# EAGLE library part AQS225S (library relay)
PhotoMOS Relay NAiS Source: http://www.mew-europe.com/.. pti_en.pdf
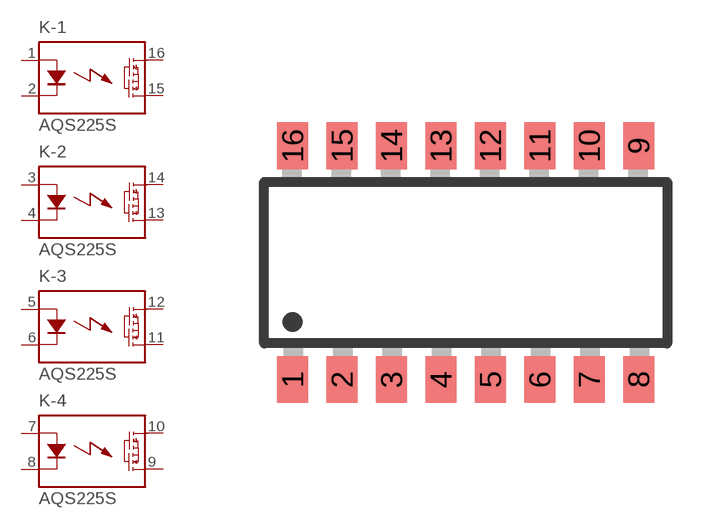
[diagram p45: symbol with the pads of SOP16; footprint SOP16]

Designator prefix K; gates -1=PHOTOMOS_2D -2=PHOTOMOS_2D -3=PHOTOMOS_2D -4=PHOTOMOS_2D

## AQS225S (MF: AROMAT/ MATSUSHITA; MPN: AQS225S; OC_FARNELL: 1448339; OC_NEWARK: 10C3715)  [SOP16]
1  -1:A  pas
2  -1:K  pas
3  -2:A  pas
4  -2:K  pas
5  -3:A  pas
6  -3:K  pas
7  -4:A  pas
8  -4:K  pas
9  -4:DS2  pas
10  -4:DS1  pas
11  -3:DS2  pas
12  -3:DS1  pas
13  -2:DS2  pas
14  -2:DS1  pas
15  -1:DS2  pas
16  -1:DS1  pas

## Footprint SOP16 (pad centres in mm)
SOP 16 - AQS21, AQS22, AQS610TS Series NAiS Source: http://www.mew-europe.com/.. pti_en.pdf
smd 0.8 x 1.2: 1 -4.445,-3; 2 -3.175,-3; 3 -1.905,-3; 4 -0.635,-3; 5 0.635,-3; 6 1.905,-3; 7 3.175,-3; 8 4.445,-3; 9 4.445,3; 10 3.175,3; 11 1.905,3; 12 0.635,3; 13 -0.635,3; 14 -1.905,3; 15 -3.175,3; 16 -4.445,3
